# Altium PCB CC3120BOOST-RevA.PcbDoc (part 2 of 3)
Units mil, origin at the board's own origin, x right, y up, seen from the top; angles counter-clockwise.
Board outline 2300 x 1700 mil, 4 copper layers (Top Layer, Mid-Layer 1, Mid-Layer 2, Bottom Layer), stack 90 mil thick; 155 components, 108 nets, 432 pads, 292 vias.
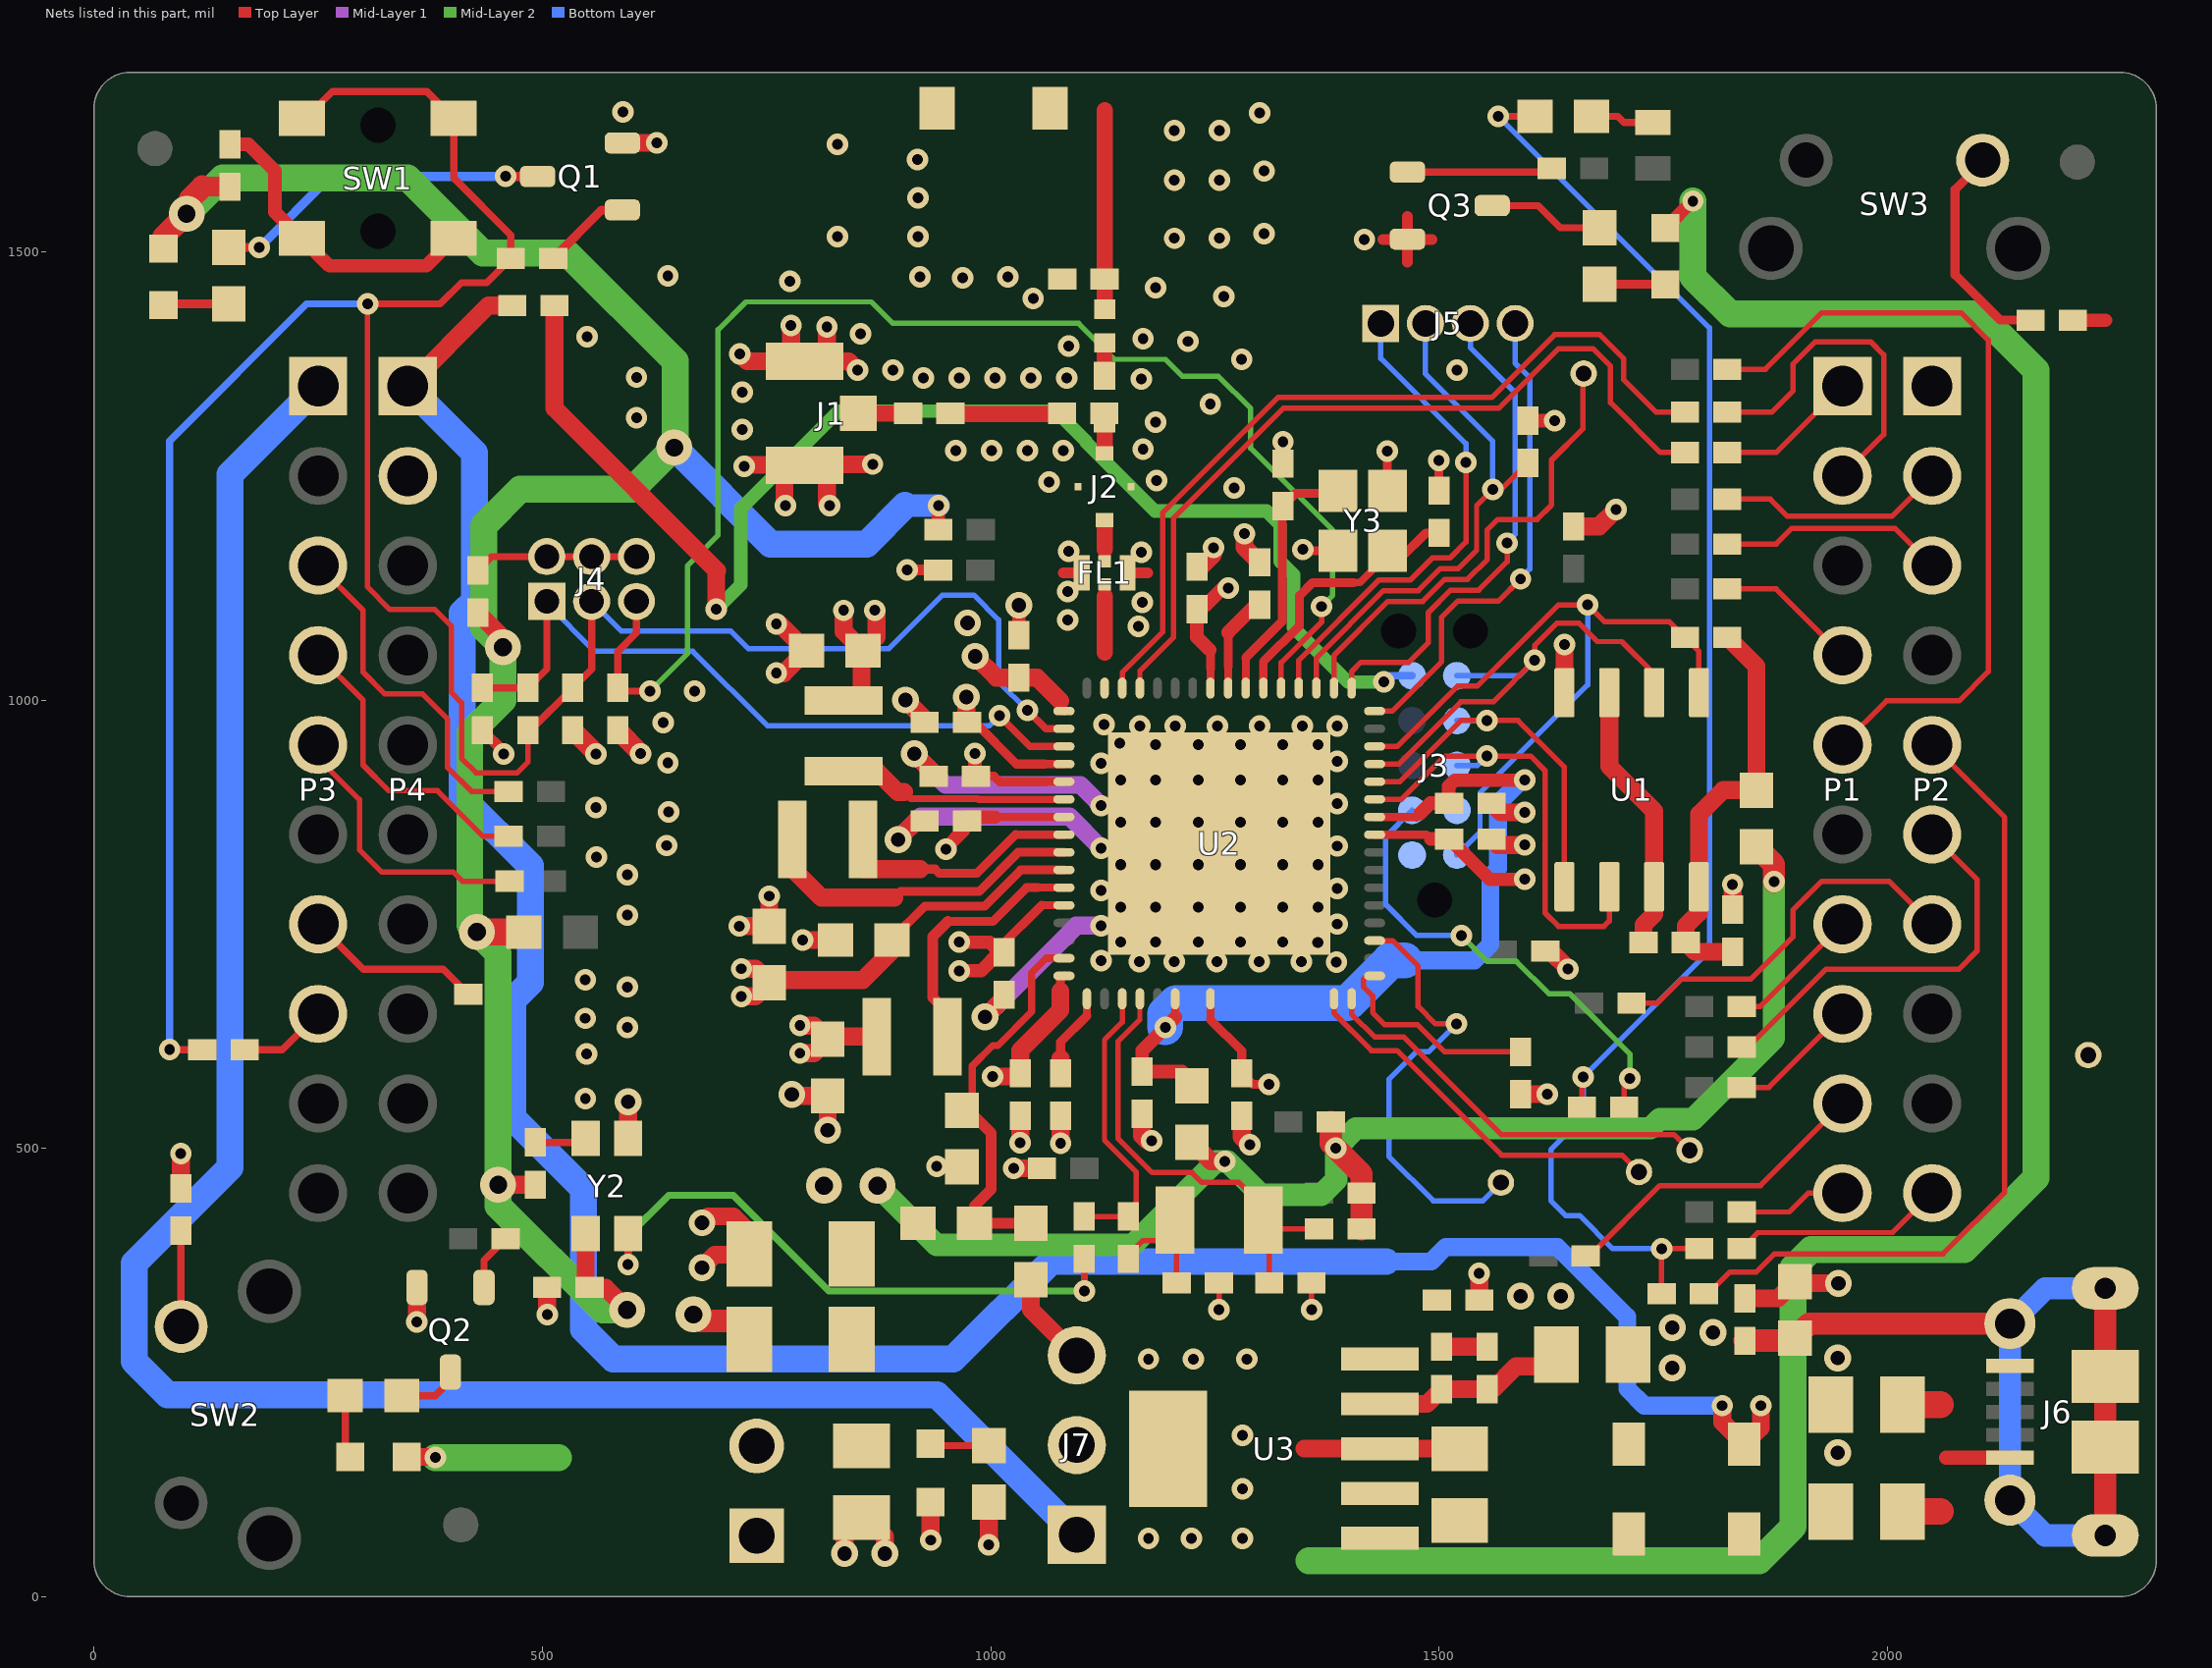
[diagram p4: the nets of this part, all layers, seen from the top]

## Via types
v1: diameter 24, hole 12, Top Layer to Bottom Layer, tented both sides, 224 vias
v2: diameter 24, hole 12.1, Top Layer to Bottom Layer, 36 vias
v3: diameter 30, hole 16, Top Layer to Bottom Layer, tented both sides, 23 vias
v4: diameter 40, hole 20, Top Layer to Bottom Layer, 9 vias

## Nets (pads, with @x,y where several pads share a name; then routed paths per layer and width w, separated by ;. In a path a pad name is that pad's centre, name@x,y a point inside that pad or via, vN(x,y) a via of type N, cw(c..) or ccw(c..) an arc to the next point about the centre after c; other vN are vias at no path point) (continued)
GND: C2.1 C2.2 C3.2 C4.2 C5.2 C6.2 C7.2 C8.2 C9.2 C10.2 C11.2 C12.2 C13.2 C14.2 C15.2 C16.2 C17.2 C18.2 C19.2 C20.2 C21.2 C22.2 C23.2 C24.2 C25.2 C26.2 C27.2 C29.2 C30.2 C31.2 C32.2 C33.2 D3.1 E1.1 E1.2 FL1.2 FL1.4 J1.2 J1.3 J2.3 J2.4 J3.1 J3.9 L1.2 L6.1 P2.1 P4.2 Q1.2 Q2.2 Q3.2 R11.2 R15.2 R16.2 R20.2 R23.2 R24.2 R25.2 R27.2 R51.1 R52.2 R61.1 R62.1 TP5.1 U1.4 U2.65 U3.3 U3.6 Y2.2 Y3.2 Y3.4 | length 3675.9
  Top Layer w6: v1(1254.66,320) C24.2@1254.66,350 ; v1(1357.83,320) C22.2@1357.83,350
  Top Layer w10: v1@1349.5,1166.54 Y3.4@1387.44,1166.54 ; Y3.2@1442.56,1233.46 v1(1442.56,1277.41) ; C25.2@1499.93,1236.71 v1(1499.93,1267.09)
  Top Layer w12: R23.2@433,966.38 457,942.38 v1(457,940) ; v1(560,940) v1@560,940.38 ; v1(609.64,940.12) v1@609.64,940.74 ; v1(907,1145) C27.2@941.38,1145 C27.2@945.71,1145 ; v1@940,479.5 C4.2@968,479.5 ; 1081,1142 FL1.2@1101.46,1142 ; FL1.4@1152.64,1142 1175,1142 ; 1437.33,1513.84 Q3.2@1464.83,1513.84 ; 1464.83,1488.33 Q3.2@1464.83,1513.84 ; 1464.83,1539.34 Q3.2@1464.83,1513.84 ; 1492.33,1513.84 Q3.2@1464.83,1513.84
  Top Layer w15: C6.2@1031.6,1072.32 v3@1031.6,1100.7 ; C26.2@1326,1259.29 C26.2@1326,1263.62 v1(1326,1288) ; R27.2@1599,1311.62 v1(1629.08,1311.62) ; R62.1@2207.08,1423.66 2243.46,1423.66
  Top Layer w18: L1.2@1127.05,1435.77 1127.05,1657.73
  Top Layer w20: R61.1@96.86,455.42 v1(96.86,494.04) ; v1(360.13,306.22) Q2.2@360.13,344.84 ; v1(505.38,314.38) C23.2@505.38,345 ; Q1.2@589.24,1621.4 v1(627.87,1621.4) ; Y2.2@595.62,511.15 v3(595.62,551.88) ; v3(678,367) 692.4,381.4 727.4,381.4 728,382 728,409.1 713.1,424 685,424 v3(678,417) ; v1(719.6,747.9) C20.2@753,747.9 v1(753,781.3) ; v1(720.39,1386) 728.57,1377.82 J1.3@784.57,1377.82 ; v1(725.34,1260.64) 727.02,1262.32 J1.2@784.02,1262.32 ; C31.2@730.4,307.83 C31.2@730.63,307.6 ; v1(761,1030) 769.5,1030 C16.2@794.5,1055 764.5,1085 v1(761,1085) ; v1(771.34,1216.64) 769.95,1218.03 769.95,1248.24 J1.2@784.02,1262.32 ; v1(777.39,1418) 777.39,1385 J1.3@784.57,1377.82 ; v3@778.2,558.5 C21.2@818.2,558.5 v3(818.2,520) ; v1(790.2,732.2) C19.2@827,732.2 ; J1.2@805.66,1262.76 868.02,1262.76 v1(868.34,1263.09) ; v1(817.39,1416) 817.39,1385 J1.3@810.21,1377.82 ; v1(820.34,1216.64) 817.34,1219.64 817.34,1250.64 805.66,1262.32 J1.2@784.02,1262.32 ; v1(851.39,1368) 841.57,1377.82 J1.3@810.21,1377.82 ; v3@896.2,844.4 916.8,865 C12.2@926.38,865 ; v3(905,1000) C17.2@926.38,978.62 ; v3(915,940) 936.38,918.62 C11.2@936.38,915 ; v1(933,63) D3.1@933,105.52 ; v3(993.8,646.5) 1015,667.7 C13.2@1015,671.38 ; v1(1025.9,477.7) R11.2@1057.28,477.7 ; v1(1033,506) C5.2@1033,536.38 ; v1(1078,505.83) C10.2@1078,536.38 ; C14.2@1168.99,538.37 1168.99,514.01 1174.6,508.4 v1(1179.4,508.4) ; C18.2@1230,1144.29 1248,1162.29 1248,1169.36 v1(1248.64,1170) ; C8.2@1280,536.38 1280,513 v1(1289,504) ; v1(1283.1,1185.4) 1283.1,1170.52 C9.2@1300,1153.62 ; 1350,165 U3.3@1434.11,165 C32.2@1523,165 ; R51.1@1544.92,330.95 v1(1544.92,360.69) ; C7.2@1558.62,845 1565.22,838.4 v1(1595.78,838.4) ; C15.2@1558.62,885 1568.98,874.65 v1(1595.78,874.65) ; R20.2@1591,560.38 v1(1620.67,560.38) ; R15.2@1613.9,720 R15.2@1618.62,720 1624.01,720 1643.67,700.35 v1(1643.67,699.78) ; U1.4@1640,1008.27 v1(1640,1062) ; R16.2@1650,1193.62 1678.62,1193.62 v1(1697.5,1212.5) ; C3.2@1827.5,766.29 v1(1827.5,794.42) ; R52.2@1841,332.62 1878.13,332.62 1895,349.5 v3(1945.5,349.5) ; J1.3@784.57,1377.82 J1.3@810.21,1377.82
  Top Layer w22: R24.2@534,966.38 v1@560,940.38 ; R25.2@584,966.38 v1@609.64,940.74
  Top Layer w25: v4(668.4,314.7) 675.5,307.6 C31.2@730.4,307.6 ; C31.2@730.4,307.83 C31.2@730.4,307.6 ; C31.2@730.63,307.6 C31.2@730.4,307.6 ; C31.2@730.91,287 730.4,287.51 C31.2@730.4,307.6
  Mid-Layer 1 w20: v3@896.2,844.4 921.8,870 1088.16,870 v1(1123.3,834.86) ; v3(915,940) 949.7,905.3 1100.1,905.3 v1(1123.3,882.1) ; v3(993.8,646.5) 1095.67,748.37 v1(1123.3,748.37)
  other v1: 1176,65 1224,65 1281,65 1281,120 1281,180 1176,265 1226,265 1286,265 940,480 548.02,555.63 549.3,605.3 595,635 548,645 595,680 548,688.07 1165.66,708.3 1204.9,708.3 1252.14,708.3 1299.39,708.3 1346.63,708.3 1385.67,707.77 1123.3,709.12 1386.49,750.12 595,760 1123.3,787.61 1386.7,789.9 595,805 560.13,824.65 1386.7,837.14 638.7,837.7 641,875 560,880 1386.7,884.39 1123.3,929.34 640,930 1386.7,931.63 1166.48,970.88 1205.72,970.88 1252.97,970.88 1300.21,970.88 1347.46,970.88 1386.7,970.88 1126.25,972.67 635,975 669.7,1009.7 1165,1082 1086,1089.44 1169,1109 1086,1121 1168,1165 1087,1166 1348.14,1167.89 1271.6,1236.6 1065,1243 1185,1245 961,1278 1001,1278 1041,1278 1081,1278 1170,1280 723,1301.55 1184.05,1310 605,1315 1245,1330 723,1343.55 1168,1358 925,1359 965,1359 1005,1359 1045,1359 1085,1359 605,1360 891,1368 1520,1368 1280,1380 1087,1395 1220,1400 1170,1403 550,1405 855,1408.55 1047.38,1447.82 1260,1450 1184.05,1460 776,1467 969,1471 921,1472 1019,1472 640,1473 1416.88,1513.48 1205,1515 1255,1515 829,1517 919,1517 1305,1520 919,1560 1205,1580 1255,1580 1305,1590 918.2,1603 829,1620 1205,1635 1255,1635 1300,1655 590,1656
  other v2: 1364.9,729.36 1144.89,729.89 1184.13,729.89 1231.38,729.89 1278.62,729.89 1325.87,729.89 1144.89,769.13 1184.13,769.13 1231.38,769.13 1278.62,769.13 1325.87,769.13 1365.11,769.13 1144.89,816.38 1184.13,816.38 1231.38,816.38 1278.62,816.38 1325.87,816.38 1365.11,816.38 1144.89,863.62 1184.13,863.62 1231.38,863.62 1278.62,863.62 1325.87,863.62 1365.11,863.62 1144.89,910.87 1184.13,910.87 1231.38,910.87 1278.62,910.87 1325.87,910.87 1365.11,910.87 1184.13,950.11 1231.38,950.11 1278.62,950.11 1325.87,950.11 1365.11,950.11 1143.9,951.9
  other v3: 1944.56,160.44 1760,255.13 1944.56,266.26 1805.55,294.45 1760,300 778.2,560 896.7,844.4 1031.6,1105.7
MCU_RESET_IN: R12.2 R37.2 R47.2 R55.2 | length 1693.2
  Top Layer w6: R12.2@1659.38,546 1659.38,578 1660.82,579.44 v1(1661,579.44) ; R37.2@1748.38,338 1748,338.38 1748,386.7 1749.3,388 R47.2@1790.38,388
  Top Layer w8: v1(1566,1651) R55.2@1607,1651
  Bottom Layer w6: v1(1566,1651) 1801.7,1415.3 1801.7,720.14 v1(1661,579.44) 1661,534.7 1624.7,498.4 1624.7,441.6 1641.3,425 1656.8,425 1693.8,388 v1(1748.38,388)
NetC1_1: C1.1 R1.2 | length 124.8
  Top Layer w18: C1.1@955.12,1319.75 955.97,1318.9 R1.2@1079.54,1318.9
NetC1_2: C1.2 J1.1 | length 55.5
  Top Layer w18: J1.1@852.37,1319.75 C1.2@907.87,1319.75
NetC3_1: C3.1 R3.1 R4.1 R7.1 U1.8 | length 464.8
  Top Layer w20: R7.1@1821.62,1070 1854,1037.62 R4.1@1854,899.5 1816.8,899.5 1790,872.7 U1.8@1790,791.73 1790,762.77 1775.33,748.1 R3.1@1775.33,729.57 1785.85,719.05 C3.1@1827.5,719.05
NetC24_1: C24.1 R17.1 Y1.1 | length 148.4
  Top Layer w6: R17.1@1153.5,376.78 1153.5,380.9 1169.6,397 1191.5,397 1205.79,411.29 Y1.1@1205.79,420 1207.42,418.37 C24.1@1207.42,350
NetC28_2: C28.2 R50.1 R51.2 U3.5 | length 51
  Top Layer w20: R50.1@1503,278.62 C28.2@1554,278.62
NetC33_1: C33.1 J6.6 J6.7 J6.8 J6.9 J6.10 J6.11 R52.1 | length 1021.3
  Top Layer w25: R52.1@1841,285.38 1893.87,285.38 C33.1@1897,288.5 1912.92,304.43 J6.10@2136.78,304.43 ; J6.6@2243.08,68.2 J6.7@2243.08,166.63 J6.8@2243.08,245.37 J6.9@2243.08,343.8
  Bottom Layer w25: J6.6@2243.08,68.2 2176.15,68.2 J6.11@2136.78,107.57 J6.10@2136.78,304.43 2176.15,343.8 J6.9@2243.08,343.8
NetD2_2: D2.2 L5.2
NetD3_2: D3.2 R49.2 | length 65.8
  Top Layer w8: D3.2@933,170.48 934.98,168.5 R49.2@998,168.5
NetD4_1: D4.1 R54.1 | length 75
  Top Layer w10: D4.1@77.5,1440.5 78.7,1441.7 R54.1@150.3,1441.7 R54.1@149.1,1440.5
NetD5_1: D5.1 R58.1 | length 70.8
  Top Layer w8: R58.1@280.25,224.23 280.25,161.25 D5.1@285.81,155.7
NetD6_1: D6.1 R57.1 | length 73.5
  Top Layer w10: R57.1@1679.21,1463.75 1752.35,1463.75 D6.1@1752.62,1463.48
NetD7_1: D7.1 R55.1 | length 71.5
  Top Layer w8: R55.1@1669.99,1651 1699.5,1651 1706.32,1644.18 D7.1@1738.68,1644.18
NetFL1_1: FL1.1 U2.31 | length 76.3
  Top Layer w12: 1127.05,1115.95 FL1.1@1127.05,1129.2
  Top Layer w18: 1127.05,1052.95 1127.05,1115.95
NetFL1_3: FL1.3 J2.1 | length 45.8
  Top Layer w12: FL1.3@1127.05,1154.8 1127.05,1168.05
  Top Layer w15: J2.1@1127.05,1193.46 J2.1@1127.05,1200.57
  Top Layer w18: 1127.05,1168.05 J2.1@1127.05,1193.46
NetJ2_2: J2.2 R1.1 R2.2 | length 43.7
  Top Layer w15: J2.2@1127.05,1275.37 1127.05,1284.67
  Top Layer w18: 1127.05,1284.67 R1.1@1127.05,1319.05
NetJ3_2: J3.2 R12.1 | length 520.8
  Top Layer w6: R12.1@1706.62,546 1706.62,571.62 v1(1713,578)
  Mid-Layer 2 w6: v1(1525.03,737.46) 1554.04,708.46 1586.58,708.46 1622.56,672.48 1645.77,672.48 1713,605.24 v1(1713,578)
  Bottom Layer w6: J3.2@1470,877.08 1440.5,847.58 1440.5,772 1475.04,737.46 v1(1525.03,737.46)
NetJ3_5: J3.5 R13.2 | length 1518.4
  Top Layer w20: R13.2@513.62,1440 513.62,1325.38 694.71,1144.29 694,1143.58 v1(694,1101.3)
  Mid-Layer 2 w15: v1(694,1101.3) 721.2,1128.5 721.2,1213.3 830.2,1322.3 1072.76,1322.3 1106.5,1288.56 1106.5,1287.44 1183.04,1210.9 1307.6,1210.9 1322.64,1195.86 1322.64,1154.86 1337.8,1139.7 1337.8,1080.85 1398.55,1020.1 v1(1438.7,1020.1)
  Bottom Layer w8: v1(1438.7,1020.1) 1445.68,1027.08 J3.5@1470,1027.08
NetJ4_1: J4.1 R21.1 R23.1 U2.35 | length 810.3
  Top Layer w8: R23.1@433,1013.62 R21.1@484,1013.62 505,1034.62 J4.1@505,1110 ; v1(1009.8,982.3) 1043.83,948.27 U2.35@1081.77,948.27
  Bottom Layer w6: J4.1@505,1110 505,1107.9 558.4,1054.5 667.8,1054.5 751.2,971.1 998.6,971.1 v1(1009.8,982.3)
NetJ4_2: J4.2 J4.4 J4.6 R22.2 | length 183.4
  Top Layer w8: R22.2@428,1144.62 443.38,1160 J4.2@505,1160 J4.4@555,1160 J4.6@605,1160
NetJ4_5: J4.5 R25.1 U2.21 | length 1606.7
  Top Layer w6: U2.21@1323.9,1013.23 1323.9,1041.67 1369.06,1086.83 v1(1369.06,1104.33)
  Top Layer w8: J4.5@605,1110 605,1075 584,1054 R25.1@584,1013.62 587.62,1010 v1(620,1010)
  Mid-Layer 2 w6: v1(620,1010) 661.7,1051.7 661.7,1149.5 696,1183.8 696,1413 727.06,1444.07 866.93,1444.07 891,1420 1098,1420 1138,1380 1195,1380 1213.7,1361.3 1253.7,1361.3 1290,1325 1290,1280.86 1381.4,1189.46 1381.4,1116.67 v1(1369.06,1104.33)
NetJ5_1: J5.1 U2.20 | length 555.4
  Top Layer w6: U2.20@1343.58,1013.23 1343.58,1044.38 1433.11,1133.91 1467.94,1133.91 1492.56,1158.54 1512.45,1158.54 1530,1176.09 v1(1530,1265)
  Bottom Layer w6: J5.1@1435,1420 1435,1381.03 1530,1286.03 v1(1530,1265)
NetJ5_2: J5.2 R27.1 U2.19 | length 605
  Top Layer w6: U2.19@1363.27,1013.23 1363.27,1047.1 1438.08,1121.91 1476.95,1121.91 1501.57,1146.54 1521.54,1146.54 1542,1167 1542,1217 v1(1560,1235) 1569.62,1235 R27.1@1599,1264.38
  Bottom Layer w6: J5.2@1485,1420 1485,1363.73 1560,1288.73 v1(1560,1235)
NetJ5_3: J5.3 U2.17 | length 552.6
  Top Layer w6: U2.17@1402.67,1013.23 1402.67,1031.67 1413,1042 1466.27,1042 1488.13,1063.85 1488.13,1097.77 1512.9,1122.54 1544.34,1122.54 1576,1154.2 v1(1576,1175)
  Bottom Layer w6: J5.3@1535,1420 1535,1393 1585,1343 1585,1185 1576,1176 v1(1576,1175)
NetJ5_4: J5.4 U2.16 | length 548.7
  Top Layer w6: U2.16@1428.23,987.64 1447.74,987.64 1503.1,1043 1503.1,1092.36 1521.28,1110.54 1566.54,1110.54 v1(1591,1135)
  Bottom Layer w6: J5.4@1585,1420 1585,1375.8 1601.2,1359.6 1601.2,1146.2 1591,1136 v1(1591,1135)
NetJ6_1: J6.1 L5.1 | length 115.9
  Top Layer w10: 2063.9,153.1 2065.62,154.82
  Top Layer w16: 2065.62,154.82 J6.1@2136.78,154.82
  Top Layer w30: L5.1@2017,95 2059.3,95
NetJ6_5: J6.5 L6.2 | length 42.3
  Top Layer w30: L6.2@2017,214 2059.3,214
NetL1_1: L1.1 R2.1 | length 41.5
  Top Layer w18: R2.1@1127,1356.9 R2.1@1127,1361.62 L1.1@1127.05,1398.37
NetL2_2: L2.2 U2.38 | length 258.8
  Top Layer w8: 903.48,897.35 910.82,890.01 945.31,890.01 985.68,889.99 986.46,889.21 U2.38@1081.77,889.21
  Top Layer w20: L2.2@836,920.63 873.17,920.63 896.45,897.35 903.48,897.35
NetL4_2: L4.2 U2.43 | length 287.3
  Top Layer w9: 1052.79,790.79 U2.43@1081.77,790.79
  Top Layer w10: 952.3,753 1002.3,753 1040.09,790.79 1052.79,790.79
  Top Layer w12: L4.2@951.77,651.73 935.4,668.1 935.4,736.1 952.3,753
  Top Layer w20: L4.2@951.77,624.6 L4.2@951.77,651.73
NetP1_1: P1.1 R29.2 | length 159
  Top Layer w6: R29.2@1821.62,1276 1876,1276 P1.1@1950,1350
NetP1_2: P1.2 R30.2 | length 384.6
  Top Layer w6: R30.2@1821.62,1321 1871,1321 1895,1345 1895,1375 1919.63,1399.63 1981.37,1399.63 1996,1385 1996,1296 P1.2@1950,1250
NetP1_4: P1.4 R34.2 | length 159
  Top Layer w6: R34.2@1821.62,1124 1876,1124 P1.4@1950,1050
NetP1_5: P1.5 R36.2 | length 896.1
  Top Layer w6: R36.2@1821.62,1369 1864,1369 1927,1432 2082.2,1432 2112.6,1401.6 2112.6,1031.6 2080,999 1999,999 P1.5@1950,950
NetP1_7: P1.7 R40.2 | length 150.5
  Top Layer w6: R40.2@1837.62,658 1858,658 P1.7@1950,750
NetP1_8: P1.8 R43.2 | length 146.3
  Top Layer w6: R43.2@1837.62,568 1868,568 P1.8@1950,650
NetP1_9: P1.9 R45.2 | length 356.8
  Top Layer w6: R45.2@1663.62,380 1667.8,380 1746.3,458.5 1858.5,458.5 P1.9@1950,550
NetP1_10: P1.10 R46.2 | length 121.1
  Top Layer w6: R46.2@1837.62,429 1890.72,429 1911.72,450 P1.10@1950,450
NetP2_2: P2.2 R31.1 | length 254.9
  Top Layer w6: R31.1@1821.62,1224 1869.53,1224 1888.53,1205 2005,1205 P2.2@2050,1250
NetP2_3: P2.3 R32.1 | length 252.8
  Top Layer w6: R32.1@1821.62,1174 1876,1174 1893.48,1191.48 2008.52,1191.48 P2.3@2050,1150
NetP2_5: P2.5 R37.1 | length 914.7
  Top Layer w6: R37.1@1795.62,338 1800.62,338 1824.62,362 1854,362 1874.2,382.2 2062.2,382.2 2130.9,450.9 2130.9,869.1 P2.5@2050,950
NetP2_6: P2.6 R39.1 | length 457.4
  Top Layer w6: R39.1@1837.62,613 1845,613 1932,700 2080,700 2100,720 2100,800 P2.6@2050,850
NetP2_7: P2.7 R41.1 | length 429.2
  Top Layer w6: R41.1@1714.62,662 1744,662 1771,689 1848,689 1894.7,735.7 1894.7,765.7 1927,798 2002,798 P2.7@2050,750
NetP2_10: P2.10 R47.1 | length 238.1
  Top Layer w6: R47.1@1837.62,388 1855.62,406 2006,406 P2.10@2050,450
NetP3_3: P3.3 R33.2 | length 388.8
  Top Layer w6: P3.3@250,1150 300,1100 300,1031 324,1007 366,1007 394,979 394,925 421,898 R33.2@462.38,898
NetP3_4: P3.4 R35.2 | length 338.5
  Top Layer w6: P3.4@250,1050 300,1000 300,927.5 328.5,899 383,899 434,848 R35.2@462.38,848
NetP3_5: P3.5 R38.2 | length 317.9
  Top Layer w6: P3.5@250,950 250,935 296,889 296,833 321,808 401,808 411,798 R38.2@463.38,798
NetP3_7: P3.7 R42.2 | length 199.9
  Top Layer w8: P3.7@250,750 300.3,699.7 389.52,699.7 R42.2@417.48,671.74
NetP3_8: P3.8 R44.2 | length 98.6
  Top Layer w8: R44.2@168,610 210,610 P3.8@250,650
NetQ1_1: Q1.1 R56.2 | length 99.5
  Top Layer w10: R56.2@512.12,1492.5 566.22,1546.6 Q1.1@589.24,1546.6
NetQ1_3: Q1.3 R54.2 | length 377.3
  Top Layer w10: R54.2@150.3,1504.7 v1(184.3,1504.7) ; v1(459,1584) Q1.3@494.76,1584
  Bottom Layer w10: v1(184.3,1504.7) 263.6,1584 v1(459,1584)
NetQ2_1: Q2.1 R59.2 | length 64.4
  Top Layer w8: Q2.1@434.93,344.84 434.93,375.21 R59.2@459.02,399.3
NetQ2_3: Q2.3 R58.2 | length 70.8
  Top Layer w6: R58.2@343.25,224.23 R58.2@343.54,223.94
  Top Layer w8: R58.2@343.54,223.94 380.49,223.94 397.53,240.98 Q2.3@397.53,250.35
NetQ3_1: Q3.1 R60.2 | length 162.8
  Top Layer w8: Q3.1@1464.83,1588.84 1621.71,1588.84 R60.2@1625.88,1593
NetQ3_3: Q3.3 R57.2 | length 130.1
  Top Layer w8: Q3.3@1559.32,1551.43 1610.76,1551.43 1635.46,1526.74 R57.2@1679.21,1526.74
NetR3_2: R3.2 U1.3 U1.7 | length 304.3
  Top Layer w20: U1.3@1690,1008.27 1690,926.05 1740,876.05 U1.7@1740,791.73 1740,761.31 1728.08,749.39 R3.2@1728.08,729.57
NetR18_2: R18.2 Y2.3 | length 58.3
  Top Layer w8: R18.2@492,506.62 543.85,506.62 Y2.3@548.38,511.15
NetR19_1: R19.1 Y2.1 | length 674
  Top Layer w8: v1(595.62,370.47) Y2.1@595.62,404.85 ; v1(1104.5,340.9) R19.1@1104.5,376.78
  Mid-Layer 2 w8: v1(595.62,370.47) 595.62,402.32 641,447.7 712.8,447.7 819.6,340.9 v1(1104.5,340.9)
NetR20_1: R20.1 U2.1 | length 238.6
  Top Layer w6: U2.1@1428.23,692.36 1419.36,692.36 1416,689 1416,680 1426,670 1426,651.3 1439.3,638 1476,638 1506.38,607.62 R20.1@1591,607.62
NetR53_1: R53.1 SW1.1 SW1.2 | length 345.6
  Top Layer w15: R53.1@151.4,1619.82 172.18,1619.82 201.7,1590.3 201.7,1544.3 231.03,1514.97 SW1.1@231.85,1514.97 262.63,1484.2 370.37,1484.2 SW1.2@401.15,1514.97
NetR61_2: R61.2 SW2.1 | length 105.9
  Top Layer w8: SW2.1@96.86,302.29 R61.2@96.86,408.17
NetR62_2: R62.2 SW3.1 | length 247.6
  Top Layer w10: SW3.1@2108.97,1602.78 2075.54,1569.36 2075.54,1474.29 2126.18,1423.66 R62.2@2159.83,1423.66
NetTP1_1: TP1.1 U2.63 | length 429.4
  Top Layer w6: U2.63@1382.95,666.77 1382.95,650.86 1424.81,609 1453.1,609 1569.8,492.3 1704.3,492.3 TP1.1@1723,473.6
NetTP2_1: TP2.1 U2.64 | length 453
  Top Layer w6: U2.64@1402.64,662.83 1402.64,649.83 1428.47,624 1460.9,624 1569.5,515.4 1762.1,515.4 TP2.1@1779.7,497.8
NetTP3_1: TP3.1 U2.18 | length 529.5
  Top Layer w6: U2.18@1382.95,1013.23 1382.95,1049.81 1443.05,1109.91 1481.92,1109.91 1506.54,1134.54 1531.74,1134.54 1554,1156.8 1554,1189.9 1565.6,1201.5 1609.5,1201.5 1625.5,1217.5 1625.5,1267.5 1660.7,1302.7 1660.7,1363.4 TP3.1@1661.4,1364.1
PA_SWN: L3.1 U2.41 | length 369.2
  Top Layer w10: 892.6,779.7 899.31,786.41 986.94,786.41 1030.69,830.16 U2.41@1081.77,830.16
  Top Layer w20: L3.1@779.63,844.4 779.63,811.37 811.3,779.7 892.6,779.7
PA_SWP: L3.2 U2.40 | length 277.1
  Top Layer w9: 1027.74,849.84 U2.40@1081.77,849.84
  Top Layer w10: 921.4,811.4 938,811.4 942.8,806.6 984.5,806.6 1027.74,849.84
  Top Layer w20: L3.2@857.57,844.4 857.57,811.4 921.4,811.4
RTC_XTAL_N: C22.1 R14.2 U2.52 Y1.2 | length 504.2
  Top Layer w6: U2.52@1166.42,666.77 1166.42,643.42 1142,619 1142,511.3 1180.3,473 1224.57,473 1235.57,462 1277,462 1304.21,434.79 Y1.2@1304.21,420 Y1.2@1310.58,413.63 ; C22.1@1310.58,350 Y1.2@1310.58,413.63 ; R14.2@1366.38,410 1314.21,410 Y1.2@1310.58,413.63
RTC_XTAL_P: R17.2 R19.2 U2.51 | length 318
  Top Layer w6: R19.2@1104.5,424.02 R17.2@1153.5,424.02 1162.1,432.62 1162.1,473.9 1127,509 1127,620.97 1146.73,640.7 U2.51@1146.73,666.77
SFL_CLK: J3.8 U1.6 U2.11 | length 532.3
  Top Layer w6: U2.11@1428.23,889.21 1458.11,889.21 1506.52,937.62 v1(1553.6,937.62) 1602.22,937.62 1618.4,921.44 1618.4,762.47 1633.36,747.5 1683.88,747.5 1690,753.62 U1.6@1690,791.73
  Bottom Layer w6: J3.8@1520,927.08 1543.05,927.08 v1(1553.6,937.62)
SFL_CS: J3.10 R7.2 U1.1 U2.14 | length 834.3
  Top Layer w6: U2.14@1428.23,948.27 1453.47,948.27 1520.77,1015.57 1542.67,1015.57 1633.25,1106.15 v1(1665.97,1106.15) 1684.81,1087.31 1757.07,1087.31 R7.2@1774.38,1070 1790,1054.38 U1.1@1790,1008.27
  Bottom Layer w6: J3.10@1520,827.08 1545.84,852.92 1545.84,896.67 1666,1016.82 v1(1665.97,1106.15)
SFL_MISO: J3.6 U1.2 U2.13 | length 524.8
  Top Layer w6: U2.13@1428.23,928.58 1454.98,928.58 1524.48,998.08 1560.74,998.08 v1(1606.83,1044.17) 1606.83,1060.87 1631.72,1085.76 1656.09,1085.76 1676.66,1065.19 1703.8,1065.19 1740,1029 U1.2@1740,1008.27
  Bottom Layer w6: J3.6@1520,1027.08 1589.74,1027.08 v1(1606.83,1044.17)
SFL_MOSI: J3.7 U1.5 U2.12 | length 428.6
  Top Layer w6: U2.12@1428.23,908.9 1456.5,908.9 1524.68,977.08 v1(1553.6,977.08) 1588.14,977.08 1640,925.22 U1.5@1640,791.73
  Bottom Layer w6: J3.7@1520,977.08 v1(1553.6,977.08)
SOP_01: J4.3 R21.2 R24.1 R44.1 R56.1 SW1.3 SW1.4 U2.34 | length 3107.6
  Top Layer w6: v1(305,1441.8) 305,1126 330,1101 380,1101 398.4,1082.6 398.4,1008.6 410,997 410,935 426,919 472,919 484,931 R21.2@484,966.38 R21.2@486.76,966.38
  Top Layer w8: v1(84.3,610) R44.1@120.76,610 ; SW1.4@231.85,1648.83 235.93,1648.83 265.8,1678.7 371.27,1678.7 SW1.3@401.15,1648.83 401.15,1582.35 464.88,1518.62 R56.1@464.88,1492.5 437.88,1465.5 409.68,1465.5 385.98,1441.8 v1(305,1441.8) ; R21.2@486.76,966.38 R24.1@534,1013.62 555,1034.62 J4.3@555,1110 ; v1(1041.1,988.33) 1061.48,967.95 U2.34@1081.77,967.95
  Bottom Layer w6: J4.3@555,1110 588.2,1076.8 710.2,1076.8 729.7,1057.3 886.4,1057.3 946.1,1117 981.2,1117 1008.9,1089.3 1008.9,1020.53 v1(1041.1,988.33)
  Bottom Layer w8: v1(84.3,610) 84.3,1288.9 237.2,1441.8 v1(305,1441.8)
TEST_03: TP4.1 U2.3 | length 497.2
  Top Layer w6: U2.3@1428.23,731.73 1448.17,731.73 1476.8,703.1 1476.8,658.2 1496.06,638.94 v1(1519.63,638.94)
  Bottom Layer w6: v1(1519.63,638.94) 1488.25,607.57 1474.57,607.57 1444.08,577.08 1444.08,491.12 1493.7,441.5 1548.9,441.5 TP4.1@1569.1,461.7
TEST_29: R29.1 U2.29 | length 925.9
  Top Layer w6: U2.29@1166.42,1013.23 1166.42,1032.52 1204,1070.1 1204,1203 1326.5,1325.5 1566.9,1325.5 1633.3,1391.9 1671.9,1391.9 1691.4,1372.4 1691.4,1331.6 1747,1276 R29.1@1774.38,1276
TEST_30: R30.1 U2.30 | length 928.8
  Top Layer w6: U2.30@1146.73,1013.23 1146.73,1030.73 1192,1076 1192,1209 1320.5,1337.5 1558.9,1337.5 1628.9,1407.5 1679.4,1407.5 1705.9,1381 1705.9,1357.4 1742.3,1321 R30.1@1774.38,1321
VBAT_CC: C11.1 C12.1 C13.1 C30.1 C31.1 J8.2 R4.2 R5.2 R8.1 R9.1 R10.2 R14.1 R48.2 U2.37 U2.39 U2.44 | length 2058
  Top Layer w9: 1005,869.53 U2.39@1081.77,869.53 ; 1056.9,771.1 U2.44@1081.77,771.1 ; 1062.1,908.9 U2.37@1081.77,908.9
  Top Layer w10: C11.1@983.62,915 1003.71,915 1009.81,908.9 1062.1,908.9 ; C13.1@1010.6,715.8 1010.6,724.8 1056.9,771.1
  Top Layer w15: v1(950,833.62) 950,835 969.29,854.29 969.29,865 973.82,869.53 1005,869.53 ; v1(965,698) 989.38,698 1010,718.62 998.62,730 v1(965,730) ; v1(982.5,940.2) 982.5,916.12 C11.1@983.62,915
  Top Layer w20: R10.2@1224.64,506.72 1245.96,485.4 v1(1261,485.4)
  Top Layer w25: R9.1@1379.33,529.34 1379.33,505.67 v1(1385,500) 1413.62,471.38 R8.1@1413.62,450 R14.1@1413.62,410 ; R4.2@1854,836.5 1873.6,816.9 v1(1873.6,797.4)
  Mid-Layer 2 w25: v4(873.8,458.2) 939.8,392.2 1158.1,392.2 1251.3,485.4 v1(1261,485.4) 1264.1,485.4 1301.3,448.2 1368.7,448.2 1385.5,465 1385.5,499.5 v1(1385,500) 1407.3,522.3 1735.9,522.3 1746.2,532.6 1783.6,532.6 1873.5,622.5 1873.5,797.3 v1(1873.6,797.4)
  other v4: 814,458.2
VCC_BRD: C23.1 D4.2 D5.2 D6.2 J7.2 J8.1 R18.1 R22.1 R26.1 R28.2 R48.1 R49.1 R53.2 Y2.4 | length 5681.3
  Top Layer w15: R26.1@941.77,1190 v1(941.77,1217) ; D6.2@1752.62,1526.47 1782.69,1556.54 v1(1783.16,1556.54)
  Top Layer w20: D5.2@344.86,155.7 D5.2@348.8,155.7 v1@380.61,155.7 ; R22.1@428,1097.38 456,1069.38 v4(456,1059) ; v4(450.75,459.38) R18.1@492,459.38 ; Y2.4@548.38,404.85 548.38,345.91 550,344.29 570.71,344.29 594.6,320.4 v4(594.6,319.7) ; v3(837,48) 837,74 R48.1@853.6,90.6 ; R48.1@856,90.6 858.4,90.6 882,67 v3(882,48) ; v1(998,58) R49.1@998,105.5
  Top Layer w22: 120.88,1572.58 R53.2@151.4,1572.58
  Top Layer w25: D4.2@77.5,1501.53 77.5,1516.5 v4(103.3,1542.3) 106.8,1545.8 106.8,1558.5 120.88,1572.58
  Top Layer w30: v4(427.1,741.22) R28.2@479.54,741.22 ; R48.1@853.6,90.6 R48.1@856,90.6
  Mid-Layer 2 w30: v4(103.3,1542.3) 143.3,1582.3 349.7,1582.3 433.4,1498.6 527.5,1498.6 648,1378.1 648,1282.5 v4(647,1281.5) 600.5,1235 475.4,1235 434.8,1194.4 434.8,1080.2 v4(456,1059) 456,999.9 419.1,963 419.1,749.22 v4(427.1,741.22) 450.75,717.57 v4(450.75,459.38) 450.75,435.95 567,319.7 v4(594.6,319.7) ; v1(380.61,155.19) 518.19,155.19 ; 1355,40 1857,40 1895,78 1895,366.86 1915.14,387 2086,387 2166,467 2166,1367.5 2103,1430.5 1824.6,1430.5 1783.16,1471.94 v1(1783.16,1556.54)
  Bottom Layer w25: 904.6,1217 v1(941.77,1217)
  Bottom Layer w30: v4(647,1281.5) 754.5,1174 861.6,1174 904.6,1217
VCC_BRD_5V: C32.1 D1.1 D2.1 U3.1 U3.2
VCC_LDO_3V3: C28.1 C29.1 J7.3 R6.2 R50.2 U3.4 | length 325.3
  Top Layer w20: R6.2@1045,353.5 1045,320 J7.3@1096,269 ; U3.4@1434.11,215 1486.62,215 R50.2@1503,231.38 C28.1@1554,231.38 1560.58,231.38 1586,256.8 1617.8,256.8 C29.1@1631,270
  other v3: 1591,335 1636,335
VCC_MCU_3V3: J7.1 P3.1 | length 2303.9
  Bottom Layer w30: P3.1@250,1350 151.5,1251.5 151.5,478.52 44.72,371.75 44.72,262.52 82.25,225 940,225 J7.1@1096,69
VCC_MCU_5V: D1.2 P4.1 R13.1 | length 2873.8
  Top Layer w20: P4.1@350,1350 440,1440 R13.1@466.38,1440 ; v1(1816,213) 1816,194.47 D1.2@1840.47,170 1858.94,188.47 v1(1858.94,213)
  Bottom Layer w20: 1440.91,373.69 1491.39,373.69 1507.7,390 1632,390 1710,312 1710,232 1729,213 v1(1816,213)
  Bottom Layer w30: P4.1@350,1350 424.2,1275.8 424.2,1110.5 410.8,1097.1 410.8,891 486.6,815.2 486.6,685 467.1,665.5 467.1,533.8 545.7,455.2 545.7,298.2 579,264.9 958.03,264.9 1066.82,373.69 1090.62,373.69 1090.83,373.9 1118.17,373.9 1118.38,373.69 1440.91,373.69
VDD_ANA: C5.1 C16.1 C17.1 C18.1 L2.1 U2.25 U2.36 U2.48 | length 639.2
  Top Layer w9: 1060.42,928.58 U2.36@1081.77,928.58 ; U2.25@1245.16,1013.23 1245.15,1034.84
  Top Layer w10: C17.1@973.62,975 982.47,975 1028.89,928.58 1060.42,928.58 ; 1077.83,675 1077.83,688.42 U2.48@1081.77,692.36 ; 1244.34,1055.82 1245.15,1055 1245.15,1034.84
  Top Layer w15: 1244.34,1055.82 1230,1070.16 C18.1@1230,1101.38 1230,1105.71 1239.81,1105.71 1259.1,1125 v1(1265,1125)
  Top Layer w20: L2.1@836,999.37 852.47,999.37 856,1002.9 856,1053.5 C16.1@857.5,1055 ; v1(836,1100) 836,1076.5 C16.1@857.5,1055 ; v1(871,1100) 872.61,1098.39 872.61,1070.11 C16.1@857.5,1055 ; v3(972.8,1003.3) 972.8,975.82 C17.1@973.62,975 ; v1(1002,580) 1029.38,580 C5.1@1033,583.62 1033,609.2 1077.83,654.03 1077.83,675
VDD_DIG_CC: C7.1 C8.1 C21.1 L4.1 U2.9 U2.56 | length 450.5
  Top Layer w9: 1245.16,643.52 U2.56@1245.16,666.77 ; U2.9@1428.23,849.84 1486.22,849.84 1491.06,845
  Top Layer w10: 1245.16,643.52 1280,608.68 C8.1@1280,583.62 1292.16,571.46 v1(1310.32,571.46)
  Top Layer w15: 1491.06,845 C7.1@1511.38,845 1511.67,845 1556.7,799.98 v1(1595.78,799.98)
  Top Layer w20: v1(787.3,606.1) 802.8,606.1 C21.1@818.2,621.5 802.8,636.89 v1(787.3,636.89) ; C21.1@818.2,624.6 L4.1@873.03,624.6
VDD_FL: C4.1 R5.1 R6.1 U2.47 | length 446.4
  Top Layer w8: C4.1@968,542.5 979.5,554 979.5,591.92 1002.28,614.7 1008.2,614.7 1045.8,652.3 1045.8,695.8 1062.05,712.05
  Top Layer w9: 1062.05,712.05 U2.47@1081.77,712.05
  Top Layer w12: C4.1@968,542.5 975.5,542.5 1000.7,517.3 1000.7,454.4 981.92,435.62 R5.1@981.92,416.59 1044.91,416.59 R6.1@1045,416.5
VDD_PA: C6.1 C19.1 C20.1 U2.33 U2.42 | length 590.8
  Top Layer w10: C19.1@888.35,731.85 926.5,770 993.15,770 1033.63,810.47 U2.42@1081.77,810.47 ; 1077.83,998.87 1077.83,991.58 U2.33@1081.77,987.64
  Top Layer w20: v1(722.1,669.51) 737.6,669.51 C20.1@753,684.9 ; v1(722.1,700.3) 737.6,700.3 C20.1@753,684.9 ; C19.1@890,730.2 890,720.4 857.4,687.8 755.9,687.8 C20.1@753,684.9 ; v3(982.6,1048.8) 1006.32,1025.08 C6.1@1031.6,1025.08 1051.62,1025.08 1077.83,998.87
  other v3: 974.3,1086
VDD_PLL: C9.1 U2.24 | length 112
  Top Layer w9: U2.24@1264.84,1013.23 1264.84,1037.84
  Top Layer w10: 1264.84,1037.84 1264.84,1074.84 1265,1075
  Top Layer w15: 1265,1075 1265,1075.71 C9.1@1300,1110.71
VDD_RAM: C10.1 U2.49 | length 99.6
  Top Layer w9: 1107.36,647.96 U2.49@1107.36,666.77
  Top Layer w10: 1078,600 1078,618.6 1107.36,647.96
  Top Layer w20: C10.1@1078,579.29 C10.1@1078,583.62 1078,600
VIN_IO: C14.1 C15.1 R10.1 U2.10 U2.54 | length 963.5
  Top Layer w9: 1205.77,646 U2.54@1205.79,666.77 ; U2.10@1428.23,869.53 1475,869.53
  Top Layer w10: 1475,869.53 1478.96,873.49
  Top Layer w15: 1206.27,646.49 1205.77,645.99 v1(1194.78,635) 1168.99,609.2 C14.1@1168.99,585.61 1213.74,585.61 R10.1@1224.64,574.71 ; 1478.96,873.49 1490.47,885 1510.71,885 1510.71,903.61 1517.73,910.63 v1(1595.78,910.63)
  Bottom Layer w20: 1462.03,709.46 1539.4,709.46 1557.3,727.36 1557.3,803.34 1565.84,811.88 1565.84,884.3 1592.17,910.63 v1(1595.78,910.63)
  Bottom Layer w40: v1(1194.78,635) 1194.78,649.78 1206.8,661.8 1397.9,661.8 1445.56,709.46 1462.03,709.46
WLAN_XTAL_N: C25.1 U2.22 Y3.1 | length 304.4
  Top Layer w8: 1404.85,1131.07 1411.88,1131.07 1427.72,1146.91 1431.64,1146.91 1442.56,1157.83 Y3.1@1457.05,1157.83
  Top Layer w9: U2.22@1304.21,1013.23 1304.22,1042.88
  Top Layer w10: 1304.21,1042.9 1344.47,1083.15 1344.47,1116.38 1359.16,1131.07 1404.85,1131.07 ; Y3.1@1457.05,1157.83 1485.6,1186.38 C25.1@1500,1186.38
WLAN_XTAL_P: C26.1 U2.23 Y3.3 | length 288.8
  Top Layer w9: U2.23@1284.53,1013.23 1284.53,1047.07
  Top Layer w10: 1284.53,1047.08 1325.14,1087.69 1325.14,1215.52 C26.1@1326,1216.38 1340.02,1230.4 1384.38,1230.4 Y3.3@1387.44,1233.46
pads on no net: FID1.1 FID2.1 FID3.1 FID4.1 FID5.1 FID6.1 J3.3 J3.4 J3.MH1 J3.MH2 J3.MH3 J6.2 J6.3 J6.4 LBL1.0 P1.3 P1.6 P2.4 P2.8 P2.9 P3.2 P3.6 P3.9 P3.10 P4.3 P4.4 P4.5 P4.6 P4.7 P4.8 P4.9 P4.10 SW1.MH1 SW1.MH2 SW2.MH1 SW2.MH2 SW3.MH1 SW3.MH2 U2.4 U2.26 U2.27 U2.28 U2.45 U2.46 U2.53

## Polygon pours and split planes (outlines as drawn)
VDD_DIG_CC on Mid-Layer 2 "Bottom Layer-VDD_DIG_CC" (solid, remove dead copper, pour order 28): 852.6,383.89 1201.1,383.89 1337.2,519.99 1343.9,526.69 1381.1,526.69 1485.19,526.69 1657.15,698.65 1657.15,820.05 1623.21,853.99 1605.1,853.99 1456.09,853.99 1417.4,815.3 1417.4,698.3 1395.99,676.89 1187.59,676.89 1049.59,538.89 1005.71,538.89 883.31,661.29 802.28,661.29 772.6,661.29 722.2,610.89 722.2,530.39 722.2,514.29 849.8,386.69
VDD_ANA on Mid-Layer 2 "Bottom Layer-VDD_ANA" (solid, remove dead copper, pour order 29): 970.6,559.8 1059,559.8 1089.9,590.7 1089.9,983.7 1108.8,1002.6 1296,1002.6 1308.3,1014.9 1308.3,1131.6 1293.7,1146.2 1217.8,1146.2 1109.1,1254.9 894.9,1254.9 884.5,1244.5 884.5,1207.1 874,1196.6 808.5,1196.6 786.7,1174.8 786.7,1097 799.3,1084.4 886.8,1084.4 923.2,1120.8 995.1,1120.8 1007.9,1108 1011.6,1104.3 1011.6,1060.8 1011.6,1033.8 999.8,1022 997.1,1019.3 968.7,1019.3 949.2,1019.3 940.8,1010.9 940.8,586 956,570.8 967,559.8
VDD_PA on Mid-Layer 2 "Bottom Layer-VDD_PA" (solid, remove dead copper, pour order 26): 659,655 763.4,655 770.2,661.8 772.6,664.2 808.8,664.2 897.4,664.2 928.7,695.5 928.7,1016.9 933.3,1021.5 941.2,1029.4 994.5,1029.4 1001.7,1036.6 1001.7,1097 990.6,1108.1 929.5,1108.1 896.4,1075 798.4,1075 779.5,1056.1 779.5,840.3 692.4,753.2 672.8,753.2 662.2,753.2 654.6,745.6 654.6,657.4 656.9,655.1
VCC_BRD on Mid-Layer 2 "Top Layer-VCC_BRD" (solid, remove dead copper, pour order 41): 470,292 470,41 490,21 1386,21 1390,25 1390,200 1375,215 919,215 834,300 775,300 765,290 765,245.2 734.8,215 675,215 650,240 636.6,253.4 636.6,325.4 620,342 612,350 598,350 521,350 488,317 470,299 470,291
GND on Mid-Layer 2 "GND-GND" (solid, remove dead copper, pour order 42): 2300,45 2255,0 35,0 0,35 0,1675 25,1700 940.2,1700 940.2,1494.65 1176.42,1494.65 1176.42,1700 2245,1700 2300,1645
VDD_PA on Top Layer "Bottom Layer-VDD_PA" (solid, remove dead copper, pour order 24): 943.6,1092.7 943.6,1040.58 961.06,1023.12 984.28,1023.12 989.7,1017.7 1000.5,1006.9 1042.9,1006.9 1054.9,1006.9 1062,1014 1062,1032.7 1054.8,1039.9 1015.84,1039.9 1006.82,1048.91 995.97,1059.77 995.97,1089.97 995.97,1099.93 989.1,1106.8 954.4,1106.8 944.3,1096.7 943.6,1096 943.6,1092.6
NetD2_2 on Top Layer "Top Layer-NetD4_2" (solid, remove dead copper, pour order 32): 1821.43,45.07 1827.52,38.99 1946.16,38.99 1963.54,56.37 1963.54,126.33 1958.88,130.99 1901.5,130.99 1894.5,123.99 1869.5,98.99 1856.5,98.99 1825.76,98.99 1821.43,94.66
NetJ6_5 on Top Layer "Top Layer-NetJ7_5" (solid, remove dead copper, pour order 30): 1991.25,246.86 2014.39,270 2159.31,270 2164.38,264.92 2164.38,249.41 2162.12,247.14 2099.9,247.14 2076.57,223.81 2076.57,185.57 2064,173 2001.29,173 1991.25,183.04
NetJ6_1 on Top Layer "Top Layer-NetJ7_1" (solid, remove dead copper, pour order 31): 1989.09,64.08 1989.09,128.09 2025,164 2026,165 2053,165 2162.3,165 2163.65,163.65 2163.65,146.44 2162.21,145 2087.51,145 2074.27,131.75 2074.27,60.27 2067,53 2000.17,53
VCC_BRD_5V on Top Layer "TOP-VCC_BRD_5V" (solid, pour order 37): 1376,55 1376,125 1386,135 1478,135 1488.01,125 1567.99,124.99 1592,149 1592,186.8 1610.2,205 1721.66,205 1738.46,188.2 1738.46,39.08 1719.38,20 1596,20 1571,45 1386,45
NetFL1_1 on Top Layer "TOP-N27756" (solid, pour order 25): 1132.73,1003 1121.36,1003 1121.36,1030.17 1121.31,1031.39 1121.15,1032.6 1120.88,1033.79 1120.52,1034.96 1120.41,1035.25 1118,1052.5 1118,1067 1136,1067 1136,1052.5 1133.54,1034.86 1133.18,1033.69 1132.92,1032.5 1132.77,1031.29 1132.73,1030.17 1132.73,1003
GND on Top Layer "TOP-GND" (solid, pour order 34): 428 vertices, not listed, extent 1927.21,1050.03 2099,1419
NetC28_2 on Top Layer "Top Layer-NetC29_2" (solid, remove dead copper, pour order 35): 1388.46,251.82 1478.11,251.82 1483.68,257.39 1486.48,260.19 1494.84,260.19 1561.19,260.19 1565,264 1565,298 1559,304 1522,304 1516.31,309.69 1513.88,312.12 1513.88,333.1 1513.88,347.85 1511.81,349.92 1409.58,349.92 1394.94,335.28 1384.38,324.72 1384.38,273.35 1384.38,254.74 1386.97,252.15
VCC_LDO_3V3 on Top Layer "Top Layer-VCC_LDO_3V3" (solid, remove dead copper, pour order 36): 1382,225 1382,205 1387,200 1482,200 1492,210 1562,210 1577,225 1657,225 1662,230 1662,345 1652,355 1577,355 1572,350 1572,255 1567,250 1492,250 1486,244 1477,235 1459,235 1387,235 1382,230 1382,224
GND on Top Layer "Top Layer-GND" (solid, remove dead copper, pour order 33): 1690,235 1770,235 1821.87,235 1821.87,315 1690,315 1685,310 1685,238 1687,236 1688,235 1691,235
VBAT_CC on Top Layer "TOP-GND" (solid, remove dead copper, pour order 38): 701.94,231 743,231 764,252 764,455.2 789.2,480.4 906.4,480.4 940.9,445.9 940.9,166.8 894.88,120.77 711.13,120.77 680.17,151.73 680.17,209.23
GND on Top Layer "Top Layer-GND" (solid, remove dead copper, pour order 39): 0,1676.08 0,25 25,0 2275.01,0.01 2300,25 2300,1669.41 2269.41,1700 23.91,1700
GND on Bottom Layer "BOTTOM-GND" (solid, remove dead copper, pour order 44): 9.17,22.83 9.17,1659.89 49.17,1699.89 949.37,1699.89 949.37,1494.54 1185.59,1494.54 1185.59,1699.89 2273.88,1699.89 2309.17,1664.6 2309.17,22.83 2286.23,-0.11 32.11,-0.11
VBAT_CC on Bottom Layer "Bottom Layer-VBAT_CC" (solid, remove dead copper, pour order 23): 800.87,433.1 898.1,433.1 1078.5,613.5 1078.5,870 1078.5,941.8 1054.52,965.78 1001.78,965.78 973.35,965.78 885.78,965.78 835,915 835,595 780.1,540.1 780.1,453.87
VCC_MCU_5V on Bottom Layer "BOTTOM-VCC_MCU_5V" (solid, pour order 43): 1907.96,219.82 1907.96,170.83 1892.96,155.83 1807.96,155.83 1787.96,175.83 1787.96,240.83 1797.96,250.83 1832.96,250.83 1842.96,240.83 1886.96,240.82
VCC_LDO_3V3 on Bottom Layer "Bottom Layer-VCC_LDO_3V3" (solid, remove dead copper, pour order 27): 1021,217 1596,217 1661,282 1661,339 1641.5,358.5 1081.7,358.5 1016,292.8 1006,282.8 1006,270.39 1006,232
GND on Mid-Layer 1 "GND-GND" (solid, remove dead copper, pour order 40): 2300,23.91 2276.09,0 204,0 45,0 0,45 0,1675.11 24.89,1700 940.2,1700 940.2,1494.65 1176.42,1494.65 1176.42,1700 2276.09,1700 2300,1676.09

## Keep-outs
Top Layer:
  circle w0: c195.41,66.07 r45
  circle w0: c195.41,341.66 r45
  circle w0: c2148.34,1504.36 r45
  circle w0: c1872.75,1504.36 r45
  rectangle: 909.25,131.27 958.75,146.73
Mid-Layer 1:
  lines w1: 940.2,1494.65 1176.42,1494.65 1176.42,1691.5 940.2,1691.5 940.2,1494.65
Mid-Layer 2:
  lines w1: 940.2,1494.65 1176.42,1494.65 1176.42,1691.5 940.2,1691.5 940.2,1494.65
Bottom Layer:
  circle w0: c2148.34,1504.36 r45
  circle w0: c1872.75,1504.36 r45
  circle w0: c195.41,66.07 r45
  circle w0: c195.41,341.66 r45
  circle w0: c316.5,1640.96 r23
  circle w0: c316.5,1522.84 r23
  lines w1: 940.2,1494.65 1176.42,1494.65 1176.42,1691.5 940.2,1691.5 940.2,1494.65
Keep-Out Layer:
  lines w10: 10,1700 2260,1700 cw(c2260,1660) 2300,1660 2300,40 cw(c2260,40) 2260,0 40,0 cw(c40,40) 0,40 0,1660 cw(c40,1660) 40,1700
  text ".Layer_Name" at 727,-858.49 h60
